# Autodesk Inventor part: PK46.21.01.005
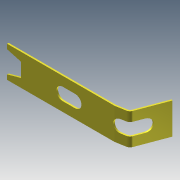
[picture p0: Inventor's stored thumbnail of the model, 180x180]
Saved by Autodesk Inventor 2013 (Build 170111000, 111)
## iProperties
Created: 2005-04
Part Number: PK46.21.01.005
Material: Steel, Mild
Document SubType Name: Sheet Metal
Designer: salex
Manufacturer: Standard
Standards Organization: Custom
Density: 7.86 g/cm^3
Sheet Metal Rule: Default
Author: salex
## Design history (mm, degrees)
node "ФлнОтгиб1"
  sketch "Эскиз1"
    geometry: L1 (2.831, 0)-(583.165, 0); L2 (583.165, 0)-(658.074, 12.834); L3 (658.074, 12.834)-(731.169, 207.98); L4 (658.074, 12.834)-(664.495, -24.645); L5 (646.711, 10.887)-(404.321, -30.641); L6 (731.169, 207.98)-(754.432, 72.205)
    constraints: 12 end point, 3 perpendicular, 1 horizontal, 1 point on line, 1 other
    dimensions: "d20" = 76 distance of L1.end L2.end; "d21" = 180 distance from line of L3.end L2; "d22" = 105 distance from line of L3.end L4; "d23" = 98 distance from line of L1.start L2; "d24" = 753 distance from line of L1.start L6
sketch "Sketch2"
  geometry: L1 (330, 140)-(250, 140); L2 (250, 60)-(330, 60); L3 (578.633, 0)-(0, 0) reference; L4 (578.633, 200)-(0, 200) reference; L5 (0, 0)-(0, 200) reference; L6 (-106.367, 199.918)-(-106.367, 169.918); L7 (-106.367, 169.918)-(-16.367, 144.959); L8 (-16.367, 54.959)-(-106.367, 30); L9 (-106.367, 30)-(-106.367, 0); L10 (-16.367, 54.959)-(-16.367, 144.959); L11 (578.633, 0)-(578.633, 200) reference; L12 (0, 0)-(-106.367, 0); L13 (0, 200)-(-106.367, 199.918); A1 r 40 centre (330, 100) between (330, 60) and (330, 140); A2 r 40 centre (250, 100) between (250, 140) and (250, 60); 1 further point
  constraints: 18 end point, 4 point on circle, 4 tangent, 2 centre point, 2 equal length, 1 collinear, 1 horizontal, 1 parallel, 1 perpendicular, 1 point on line, 1 vertical
  dimensions: "d25" = 80 distance of A1.centre A2.centre; "d26" = 40 radius of A2; "d27" = 200 distance between parallel lines of L3 L4 (derived); "d28" = 100 distance from line of A2.centre L4 (= 0.5 x d27); "d29" = 250 distance from line of A2.centre L5; "d32" = 30 distance of L8.end L9.end; "d33" = 90 distance of L8.start L7.end; "d34" = 90 distance between parallel lines of L6 L10; "d35" = 105.5 deg angle of L10 L8; "d37" = 685 distance between parallel lines of L9 L11
cut "Cut1" dims "d30" = 10 (= Thickness), "d31" = 0
node "Face1"
sketch "Sketch3"
  geometry: L1 (30.937, 60)-(150.937, 60); L2 (150.937, 140)-(30.937, 140); L3 (187.937, 0)-(187.937, 200) reference; L4 (187.937, 0)-(88.725, 0) reference; A1 r 40 centre (30.937, 100) between (30.937, 140) and (30.937, 60); A2 r 40 centre (150.937, 100) between (150.937, 60) and (150.937, 140); 1 further point
  constraints: 4 end point, 4 point on circle, 4 tangent, 2 centre point, 1 horizontal, 1 parallel
  dimensions: "d43" = 120 distance of A2.centre A1.centre; "d44" = 40 radius of A1; "d45" = 200 distance of L3.start L3.end (derived); "d46" = 100 distance from line of A2.centre L4 (= 0.5 x d45); "d47" = 37 distance from line of A2.centre L3
cut "Cut2" sketch "Sketch3" dims "d48" = 10 (= Thickness), "d49" = 0
body "Solid1"
face "Плакирование1" dims "d13" = 200, "d14" = 10 (= BendReliefWidth), "d16" = 20 (= MinimumRemnant), "d18" = 20 (= BendRadius), "d19" = 10, "Thickness" = 10
bend "Изгиб1" dims "d14" = 10 (= BendReliefWidth), "d15" = 5 (= BendReliefDepth), "d16" = 20 (= MinimumRemnant), "d17" = 20 (= BendRadius), "d18" = 20 (= BendRadius), "d19" = 10, "SeamGap" = 0.01, "Thickness" = 10
face "Plate2" dims "d38" = 20 (= BendRadius), "d39" = 10 (= BendReliefWidth), "d41" = 20 (= MinimumRemnant), "Thickness" = 10
bend "Bend2" dims "d38" = 20 (= BendRadius), "d39" = 10 (= BendReliefWidth), "d40" = 5 (= BendReliefDepth), "d41" = 20 (= MinimumRemnant), "d42" = 20 (= BendRadius), "SeamGap" = 0.01, "Thickness" = 10
other parameters: "BendRadius" = 20, "BendReliefDepth" = 5 (= 0.5 x Thickness)
